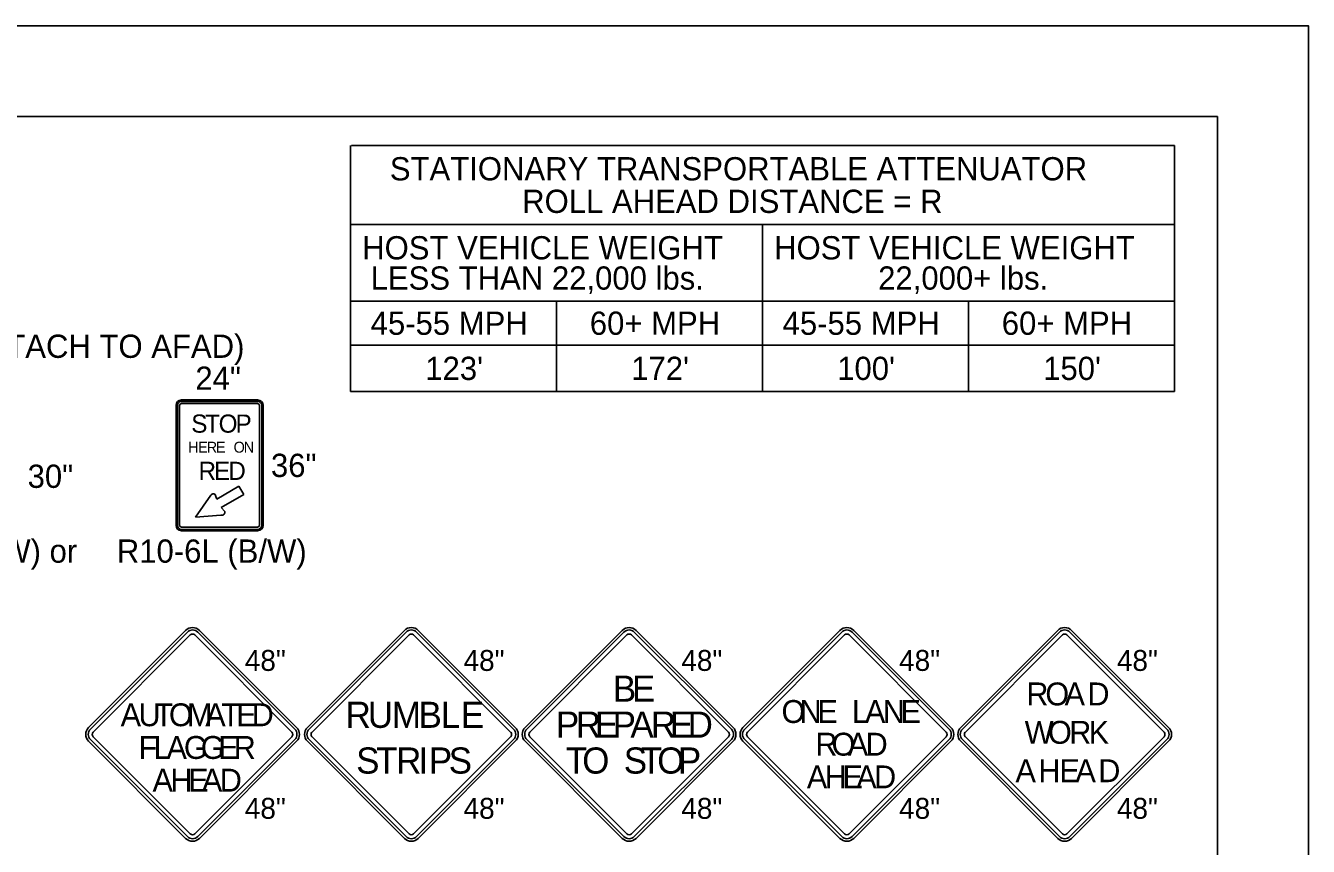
# Model space of a CAD drawing. Extents: x 99999.1 to 100095.7, y 99995 to 100010.7.
# Drawn here: x 100051.645 to 100056.062, y 100007.863 to 100010.687 of the extents above; entities that cross this region are included whole.
import ezdxf

# ---------------------------------------------------------------- set-up
doc = ezdxf.new("R2010")
doc.units = 0
for name, color, linetype in [('Default', 7, 'Continuous'), ('SH_GI_PlotLimits', 7, 'Continuous'), ('SH_GI_SheetBorder', 7, 'Continuous'), ('SH_TI_Tables', 7, 'Continuous'), ('TR_SN_ConstructionSigns', 7, 'Continuous'), ('TR_WZ_WorkZoneDetails', 7, 'Continuous')]:
    doc.layers.add(name, color=color, linetype=linetype)

msp = doc.modelspace()

# ---------------------------------------------------------------- linework, layer by layer
at = {"layer": 'Default'}
for p, q in [((100052.9495, 100008.6062), (100052.6154, 100008.2721)), ((100053.3313, 100008.2721), (100052.9972, 100008.6062)), ((100052.6154, 100008.2243), (100052.9495, 100007.8902)), ((100052.9972, 100007.8902), (100053.3313, 100008.2243))]:
    msp.add_line(p, q, dxfattribs=at)
for centre, start, end in [((100052.9733, 100008.5823), 45, 135), ((100052.6392, 100008.2482), 135, 225), ((100053.3075, 100008.2482), 315, 45), ((100052.9733, 100007.9141), 225, 315)]:
    msp.add_arc(centre, 0.0338, start, end, dxfattribs=at)
at = {"layer": 'SH_GI_PlotLimits'}
msp.add_lwpolyline([(100039.0625, 99999.6875), (100056.0625, 99999.6875), (100056.0625, 100010.6875), (100039.0625, 100010.6875)], close=True, dxfattribs=at)
at = {"layer": 'SH_GI_SheetBorder'}
for p, q in [((100040, 100010.375), (100055.75, 100010.375)), ((100055.75, 100010.375), (100055.75, 100000))]:
    msp.add_line(p, q, dxfattribs=at)
at = {"layer": 'SH_TI_Tables'}
for p, q in [((100052.764, 100009.428), (100052.764, 100010.275)), ((100052.767, 100010.275), (100055.6015, 100010.275)), ((100055.6015, 100009.428), (100055.6015, 100010.275)), ((100052.764, 100010.003), (100055.6015, 100010.003)), ((100054.1827, 100009.428), (100054.1827, 100010.003)), ((100052.764, 100009.7389), (100054.1827, 100009.7389)), ((100053.4734, 100009.428), (100053.4734, 100009.7389)), ((100054.1827, 100009.7389), (100055.6015, 100009.7389)), ((100054.8921, 100009.428), (100054.8921, 100009.7389)), ((100052.764, 100009.588), (100054.1827, 100009.588)), ((100054.1827, 100009.588), (100055.6015, 100009.588)), ((100052.764, 100009.428), (100055.6015, 100009.428))]:
    msp.add_line(p, q, dxfattribs=at)
at = {"layer": 'TR_SN_ConstructionSigns'}
for p, q in [((100052.4441, 100009.3991), (100052.1816, 100009.3991)), ((100052.1816, 100009.3991), (100052.4441, 100009.3991)), ((100052.4441, 100009.3991), (100052.1816, 100009.3991)), ((100052.1629, 100009.3804), (100052.1629, 100008.9679)), ((100052.1629, 100008.9679), (100052.1629, 100009.3804)), ((100052.1629, 100009.3804), (100052.1629, 100008.9679)), ((100052.1676, 100009.3804), (100052.1676, 100008.9679)), ((100052.1754, 100008.9679), (100052.1754, 100009.3804)), ((100052.4441, 100009.3944), (100052.1816, 100009.3944)), ((100052.1816, 100009.3866), (100052.4441, 100009.3866)), ((100052.4504, 100009.3804), (100052.4504, 100008.9679)), ((100052.4582, 100008.9679), (100052.4582, 100009.3804)), ((100052.4629, 100008.9679), (100052.4629, 100009.3804)), ((100052.4629, 100009.3804), (100052.4629, 100008.9679)), ((100052.4629, 100008.9679), (100052.4629, 100009.3804)), ((100052.3796, 100009.1022), (100052.303, 100009.058)), ((100052.396, 100009.0738), (100052.3796, 100009.1022)), ((100052.2824, 100009.0718), (100052.2298, 100008.9961)), ((100052.303, 100009.058), (100052.2992, 100009.0706)), ((100052.3186, 100009.0291), (100052.396, 100009.0738)), ((100052.2298, 100008.9961), (100052.3176, 100009.0022)), ((100052.3309, 100009.0154), (100052.3186, 100009.0291)), ((100052.4441, 100008.9616), (100052.1816, 100008.9616)), ((100052.1816, 100008.9538), (100052.4441, 100008.9538)), ((100052.1816, 100008.9491), (100052.4441, 100008.9491)), ((100052.4441, 100008.9491), (100052.1816, 100008.9491)), ((100052.1816, 100008.9491), (100052.4441, 100008.9491)), ((100052.1961, 100008.6062), (100051.862, 100008.2721)), ((100052.5779, 100008.2721), (100052.2438, 100008.6062)), ((100052.6154, 100008.2721), (100052.9495, 100008.6062)), ((100052.9972, 100008.6062), (100053.3313, 100008.2721)), ((100053.3654, 100008.2721), (100053.6995, 100008.6062)), ((100053.7472, 100008.6062), (100054.0813, 100008.2721)), ((100054.1154, 100008.2721), (100054.4495, 100008.6062)), ((100054.4972, 100008.6062), (100054.8313, 100008.2721)), ((100054.8654, 100008.2721), (100055.1995, 100008.6062)), ((100055.2472, 100008.6062), (100055.5813, 100008.2721)), ((100052.2021, 100008.6002), (100051.868, 100008.2661)), ((100051.8779, 100008.2561), (100052.212, 100008.5903)), ((100052.2279, 100008.5903), (100052.562, 100008.2561)), ((100052.572, 100008.2661), (100052.2379, 100008.6002)), ((100052.9555, 100008.6002), (100052.6213, 100008.2661)), ((100052.6313, 100008.2561), (100052.9654, 100008.5903)), ((100052.9813, 100008.5903), (100053.3154, 100008.2561)), ((100053.3254, 100008.2661), (100052.9912, 100008.6002)), ((100053.7055, 100008.6002), (100053.3713, 100008.2661)), ((100053.3813, 100008.2561), (100053.7154, 100008.5903)), ((100053.7313, 100008.5903), (100054.0654, 100008.2561)), ((100054.0754, 100008.2661), (100053.7412, 100008.6002)), ((100054.4555, 100008.6002), (100054.1213, 100008.2661)), ((100054.1313, 100008.2561), (100054.4654, 100008.5903)), ((100054.4813, 100008.5903), (100054.8154, 100008.2561)), ((100054.8254, 100008.2661), (100054.4912, 100008.6002)), ((100055.2055, 100008.6002), (100054.8713, 100008.2661)), ((100054.8813, 100008.2561), (100055.2154, 100008.5903)), ((100055.2313, 100008.5903), (100055.5654, 100008.2561)), ((100055.5754, 100008.2661), (100055.2412, 100008.6002)), ((100051.862, 100008.2243), (100052.1961, 100007.8902)), ((100051.868, 100008.2303), (100052.2021, 100007.8962)), ((100052.212, 100007.9061), (100051.8779, 100008.2402)), ((100052.562, 100008.2402), (100052.2279, 100007.9061)), ((100052.2379, 100007.8962), (100052.572, 100008.2303)), ((100052.2438, 100007.8902), (100052.5779, 100008.2243)), ((100052.9495, 100007.8902), (100052.6154, 100008.2243)), ((100052.6213, 100008.2303), (100052.9555, 100007.8962)), ((100052.9654, 100007.9061), (100052.6313, 100008.2402)), ((100053.3154, 100008.2402), (100052.9813, 100007.9061)), ((100052.9912, 100007.8962), (100053.3254, 100008.2303)), ((100053.3313, 100008.2243), (100052.9972, 100007.8902)), ((100053.6995, 100007.8902), (100053.3654, 100008.2243)), ((100053.3713, 100008.2303), (100053.7055, 100007.8962)), ((100053.7154, 100007.9061), (100053.3813, 100008.2402)), ((100054.0654, 100008.2402), (100053.7313, 100007.9061)), ((100053.7412, 100007.8962), (100054.0754, 100008.2303)), ((100054.0813, 100008.2243), (100053.7472, 100007.8902)), ((100054.4495, 100007.8902), (100054.1154, 100008.2243)), ((100054.1213, 100008.2303), (100054.4555, 100007.8962)), ((100054.4654, 100007.9061), (100054.1313, 100008.2402)), ((100054.8154, 100008.2402), (100054.4813, 100007.9061)), ((100054.4912, 100007.8962), (100054.8254, 100008.2303)), ((100054.8313, 100008.2243), (100054.4972, 100007.8902)), ((100055.1995, 100007.8902), (100054.8654, 100008.2243)), ((100054.8713, 100008.2303), (100055.2055, 100007.8962)), ((100055.2154, 100007.9061), (100054.8813, 100008.2402)), ((100055.5654, 100008.2402), (100055.2313, 100007.9061)), ((100055.2412, 100007.8962), (100055.5754, 100008.2303)), ((100055.5813, 100008.2243), (100055.2472, 100007.8902))]:
    msp.add_line(p, q, dxfattribs=at)
for centre, radius, start, end in [((100052.1816, 100009.3804), 0.0187, 90, 180), ((100052.1816, 100009.3804), 0.0187, 90, 180), ((100052.1816, 100009.3804), 0.0187, 90, 180), ((100052.4441, 100009.3804), 0.0187, 0, 90), ((100052.4441, 100009.3804), 0.0187, 0, 90), ((100052.4441, 100009.3804), 0.0187, 0, 90), ((100052.1816, 100009.3804), 0.0141, 90, 180), ((100052.1816, 100009.3804), 0.00625, 90, 180), ((100052.4441, 100009.3804), 0.0141, 0, 90), ((100052.4441, 100009.3804), 0.00625, 0, 90), ((100052.1816, 100008.9679), 0.0187, 180, 270), ((100052.1816, 100008.9679), 0.0187, 180, 270), ((100052.1816, 100008.9679), 0.0187, 180, 270), ((100052.1816, 100008.9679), 0.0141, 180, 270), ((100052.1816, 100008.9679), 0.00625, 180, 270), ((100052.4441, 100008.9679), 0.0187, 270, 0), ((100052.4441, 100008.9679), 0.0187, 270, 0), ((100052.4441, 100008.9679), 0.0187, 270, 0), ((100052.4441, 100008.9679), 0.0141, 270, 0), ((100052.4441, 100008.9679), 0.00625, 270, 0), ((100052.22, 100008.5823), 0.0338, 45, 135), ((100052.22, 100008.5823), 0.0253, 45, 135), ((100052.9733, 100008.5823), 0.0338, 45, 135), ((100052.9733, 100008.5823), 0.0253, 45, 135), ((100053.7233, 100008.5823), 0.0338, 45, 135), ((100053.7233, 100008.5823), 0.0253, 45, 135), ((100054.4733, 100008.5823), 0.0338, 45, 135), ((100054.4733, 100008.5823), 0.0253, 45, 135), ((100055.2233, 100008.5823), 0.0338, 45, 135), ((100055.2233, 100008.5823), 0.0253, 45, 135), ((100052.22, 100008.5823), 0.0113, 45, 135), ((100052.9733, 100008.5823), 0.0113, 45, 135), ((100053.7233, 100008.5823), 0.0113, 45, 135), ((100054.4733, 100008.5823), 0.0113, 45, 135), ((100055.2233, 100008.5823), 0.0113, 45, 135), ((100051.8859, 100008.2482), 0.0338, 135, 225), ((100051.8859, 100008.2482), 0.0253, 135, 225), ((100051.8859, 100008.2482), 0.0113, 135, 225), ((100052.5541, 100008.2482), 0.0113, 315, 45), ((100052.5541, 100008.2482), 0.0253, 315, 45), ((100052.5541, 100008.2482), 0.0338, 315, 45), ((100052.6392, 100008.2482), 0.0338, 135, 225), ((100052.6392, 100008.2482), 0.0253, 135, 225), ((100052.6392, 100008.2482), 0.0113, 135, 225), ((100053.3075, 100008.2482), 0.0113, 315, 45), ((100053.3075, 100008.2482), 0.0253, 315, 45), ((100053.3075, 100008.2482), 0.0338, 315, 45), ((100053.3892, 100008.2482), 0.0338, 135, 225), ((100053.3892, 100008.2482), 0.0253, 135, 225), ((100053.3892, 100008.2482), 0.0113, 135, 225), ((100054.0575, 100008.2482), 0.0113, 315, 45), ((100054.0575, 100008.2482), 0.0253, 315, 45), ((100054.0575, 100008.2482), 0.0338, 315, 45), ((100054.1392, 100008.2482), 0.0338, 135, 225), ((100054.1392, 100008.2482), 0.0253, 135, 225), ((100054.1392, 100008.2482), 0.0113, 135, 225), ((100054.8075, 100008.2482), 0.0113, 315, 45), ((100054.8075, 100008.2482), 0.0253, 315, 45), ((100054.8075, 100008.2482), 0.0338, 315, 45), ((100054.8892, 100008.2482), 0.0338, 135, 225), ((100054.8892, 100008.2482), 0.0253, 135, 225), ((100054.8892, 100008.2482), 0.0113, 135, 225), ((100055.5575, 100008.2482), 0.0113, 315, 45), ((100055.5575, 100008.2482), 0.0253, 315, 45), ((100055.5575, 100008.2482), 0.0338, 315, 45), ((100052.22, 100007.9141), 0.0113, 225, 315), ((100052.9733, 100007.9141), 0.0113, 225, 315), ((100053.7233, 100007.9141), 0.0113, 225, 315), ((100054.4733, 100007.9141), 0.0113, 225, 315), ((100055.2233, 100007.9141), 0.0113, 225, 315), ((100052.22, 100007.9141), 0.0338, 225, 315), ((100052.22, 100007.9141), 0.0253, 225, 315), ((100052.9733, 100007.9141), 0.0338, 225, 315), ((100052.9733, 100007.9141), 0.0253, 225, 315), ((100053.7233, 100007.9141), 0.0338, 225, 315), ((100053.7233, 100007.9141), 0.0253, 225, 315), ((100054.4733, 100007.9141), 0.0338, 225, 315), ((100054.4733, 100007.9141), 0.0253, 225, 315), ((100055.2233, 100007.9141), 0.0338, 225, 315), ((100055.2233, 100007.9141), 0.0253, 225, 315)]:
    msp.add_arc(centre, radius, start, end, dxfattribs=at)
for centre, major_axis, start_param, end_param in [((100052.2891, 100009.0675), (0.00934, 0.00539), 5.977036, 8.198856), ((100052.3216, 100009.0104), (-0.00913, -0.00527), 0.771965, 3.092601)]:
    msp.add_ellipse(centre, major_axis=major_axis, ratio=0.700347, start_param=start_param, end_param=end_param, dxfattribs=at)
at = {"layer": 'TR_WZ_WorkZoneDetails'}
for p, q in [((100053.6995, 100008.6062), (100053.3654, 100008.2721)), ((100054.0813, 100008.2721), (100053.7472, 100008.6062)), ((100054.4495, 100008.6062), (100054.1154, 100008.2721)), ((100054.8313, 100008.2721), (100054.4972, 100008.6062)), ((100055.1995, 100008.6062), (100054.8654, 100008.2721)), ((100055.5813, 100008.2721), (100055.2472, 100008.6062)), ((100053.3654, 100008.2243), (100053.6995, 100007.8902)), ((100053.7472, 100007.8902), (100054.0813, 100008.2243)), ((100054.1154, 100008.2243), (100054.4495, 100007.8902)), ((100054.4972, 100007.8902), (100054.8313, 100008.2243)), ((100054.8654, 100008.2243), (100055.1995, 100007.8902)), ((100055.2472, 100007.8902), (100055.5813, 100008.2243))]:
    msp.add_line(p, q, dxfattribs=at)
for centre, start, end in [((100053.7233, 100008.5823), 45, 135), ((100054.4733, 100008.5823), 45, 135), ((100055.2233, 100008.5823), 45, 135), ((100053.3892, 100008.2482), 135, 225), ((100054.0575, 100008.2482), 315, 45), ((100054.1392, 100008.2482), 135, 225), ((100054.8075, 100008.2482), 315, 45), ((100054.8892, 100008.2482), 135, 225), ((100055.5575, 100008.2482), 315, 45), ((100053.7233, 100007.9141), 225, 315), ((100054.4733, 100007.9141), 225, 315), ((100055.2233, 100007.9141), 225, 315)]:
    msp.add_arc(centre, 0.0338, start, end, dxfattribs=at)

# ---------------------------------------------------------------- texts
at = {"layer": 'Default'}
for s, p in [('R', (100052.747, 100008.2707)), ('U', (100052.8235, 100008.2707)), ('M', (100052.9063, 100008.2707)), ('B', (100052.9981, 100008.2707)), ('L', (100053.0746, 100008.2707)), ('E', (100053.1439, 100008.2707)), ('S', (100052.7834, 100008.1132)), ('T', (100052.8518, 100008.1132)), ('R', (100052.9211, 100008.1132)), ('I', (100052.9976, 100008.1132)), ('P', (100053.0336, 100008.1132)), ('S', (100053.102, 100008.1132))]:
    msp.add_text(s, height=0.09, dxfattribs=at).set_placement(p)
at = {"layer": 'SH_TI_Tables'}
for s, p in [('STATIONARY TRANSPORTABLE ATTENUATOR', (100052.8993, 100010.155)), ('ROLL AHEAD DISTANCE = R', (100053.355, 100010.043)), ('HOST VEHICLE WEIGHT', (100052.804, 100009.883)), ('HOST VEHICLE WEIGHT', (100054.2227, 100009.883)), ('LESS THAN 22,000 lbs.', (100052.8332, 100009.7789)), ('22,000+ lbs.', (100054.581, 100009.7789)), ('45-55 MPH', (100052.8333, 100009.6234)), ('60+ MPH', (100053.588, 100009.6234)), ('45-55 MPH', (100054.252, 100009.6234)), ('60+ MPH', (100055.0067, 100009.6234)), ("123'", (100053.0213, 100009.468)), ("172'", (100053.7306, 100009.468)), ("100'", (100054.44, 100009.468)), ("150'", (100055.1493, 100009.468))]:
    msp.add_text(s, height=0.08, dxfattribs=at).set_placement(p)
at = {"layer": 'TR_SN_ConstructionSigns'}
for s, height, p in [('(MAY ATTACH TO AFAD)', 0.08, (100051.1446, 100009.5441)), ('24"', 0.08, (100052.2295, 100009.4341)), ('36"', 0.08, (100052.4898, 100009.1341)), ('30"', 0.08, (100051.6518, 100009.0966)), ('R10-6A (B/W) or', 0.08, (100051.032, 100008.8391)), ('R10-6L (B/W)', 0.08, (100051.959, 100008.8391)), ('48"', 0.072, (100052.3998, 100008.4667)), ('48"', 0.072, (100053.1531, 100008.4667)), ('48"', 0.072, (100053.9031, 100008.4667)), ('48"', 0.072, (100054.6531, 100008.4667)), ('48"', 0.072, (100055.4031, 100008.4667)), ('48"', 0.072, (100052.3998, 100007.9576)), ('48"', 0.072, (100053.1531, 100007.9576)), ('48"', 0.072, (100053.9031, 100007.9576)), ('48"', 0.072, (100054.6531, 100007.9576)), ('48"', 0.072, (100055.4031, 100007.9576))]:
    msp.add_text(s, height=height, rotation=360, dxfattribs=at).set_placement(p)
for s, height, p in [('S', 0.0625, (100052.2154, 100009.2866)), ('T', 0.0625, (100052.2629, 100009.2866)), ('O', 0.0625, (100052.3097, 100009.2866)), ('P', 0.0625, (100052.3679, 100009.2866)), ('H', 0.0375, (100052.2043, 100009.2179)), ('E', 0.0375, (100052.2388, 100009.2179)), ('R', 0.0375, (100052.2684, 100009.2179)), ('E', 0.0375, (100052.3003, 100009.2179)), ('O', 0.0375, (100052.3611, 100009.2179)), ('N', 0.0375, (100052.3959, 100009.2179)), ('R', 0.0625, (100052.2404, 100009.1241)), ('E', 0.0625, (100052.2935, 100009.1241)), ('D', 0.0625, (100052.3429, 100009.1241)), ('A', 0.0787, (100051.9723, 100008.2763)), ('U', 0.0787, (100052.0337, 100008.2763)), ('T', 0.0787, (100052.0888, 100008.2763)), ('O', 0.0787, (100052.1385, 100008.2763)), ('M', 0.0787, (100052.2007, 100008.2763)), ('A', 0.0787, (100052.2637, 100008.2763)), ('T', 0.0787, (100052.3188, 100008.2763)), ('E', 0.0787, (100052.37, 100008.2763)), ('D', 0.0787, (100052.4235, 100008.2763)), ('F', 0.0787, (100052.0341, 100008.1638)), ('L', 0.0787, (100052.0853, 100008.1638)), ('A', 0.0787, (100052.1302, 100008.1638)), ('G', 0.0787, (100052.19, 100008.1638)), ('G', 0.0787, (100052.2483, 100008.1638)), ('E', 0.0787, (100052.3082, 100008.1638)), ('R', 0.0787, (100052.3617, 100008.1638)), ('A', 0.0787, (100052.0821, 100008.0513)), ('H', 0.0787, (100052.1436, 100008.0513)), ('E', 0.0787, (100052.205, 100008.0513)), ('A', 0.0787, (100052.2522, 100008.0513)), ('D', 0.0787, (100052.3137, 100008.0513))]:
    msp.add_text(s, height=height, dxfattribs=at).set_placement(p)
at = {"layer": 'TR_WZ_WorkZoneDetails'}
for s, height, p in [('B', 0.09, (100053.6675, 100008.3607)), ('E', 0.09, (100053.7332, 100008.3607)), ('O', 0.0788, (100055.1568, 100008.348)), ('R', 0.0788, (100055.0914, 100008.348)), ('A', 0.0788, (100055.223, 100008.348)), ('D', 0.0788, (100055.3017, 100008.348)), ('O', 0.0787, (100054.2481, 100008.2876)), ('N', 0.0787, (100054.3103, 100008.2876)), ('E', 0.0787, (100054.3718, 100008.2876)), ('L', 0.0787, (100054.4907, 100008.2876)), ('A', 0.0787, (100054.5356, 100008.2876)), ('N', 0.0787, (100054.597, 100008.2876)), ('E', 0.0787, (100054.6584, 100008.2876)), ('P', 0.09, (100053.4713, 100008.2369)), ('R', 0.09, (100053.5397, 100008.2369)), ('E', 0.09, (100053.6054, 100008.2369)), ('P', 0.09, (100053.6666, 100008.2369)), ('A', 0.09, (100053.7278, 100008.2369)), ('R', 0.09, (100053.798, 100008.2369)), ('E', 0.09, (100053.8637, 100008.2369)), ('D', 0.09, (100053.9249, 100008.2369)), ('O', 0.0788, (100055.1659, 100008.2158)), ('R', 0.0787, (100054.3647, 100008.1751)), ('O', 0.0787, (100054.4206, 100008.1751)), ('A', 0.0787, (100054.4765, 100008.1751)), ('D', 0.0787, (100054.5379, 100008.1751)), ('W', 0.0788, (100055.0855, 100008.2158)), ('R', 0.0788, (100055.2391, 100008.2158)), ('K', 0.0788, (100055.306, 100008.2158)), ('T', 0.09, (100053.5051, 100008.1132)), ('O', 0.09, (100053.5618, 100008.1132)), ('S', 0.09, (100053.7049, 100008.1132)), ('T', 0.09, (100053.7634, 100008.1132)), ('O', 0.09, (100053.8201, 100008.1132)), ('P', 0.09, (100053.8912, 100008.1132)), ('A', 0.0788, (100055.054, 100008.0837)), ('H', 0.0788, (100055.1328, 100008.0837)), ('E', 0.0788, (100055.2052, 100008.0837)), ('A', 0.0788, (100055.2604, 100008.0837)), ('D', 0.0788, (100055.3391, 100008.0837)), ('A', 0.0787, (100054.3355, 100008.0626)), ('H', 0.0787, (100054.397, 100008.0626)), ('E', 0.0787, (100054.4584, 100008.0626)), ('A', 0.0787, (100054.5056, 100008.0626)), ('D', 0.0787, (100054.5671, 100008.0626))]:
    msp.add_text(s, height=height, dxfattribs=at).set_placement(p)

doc.saveas('drawing.dxf')
